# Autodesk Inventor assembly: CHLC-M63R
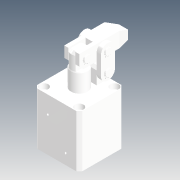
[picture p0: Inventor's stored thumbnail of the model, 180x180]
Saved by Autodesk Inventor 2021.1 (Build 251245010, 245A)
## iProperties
Created: 2019-04
Part Number: CHLC-M63R
Description: STEP AP214
Document SubType Name: Assembly
Designer: user
Title: chlc-m63_asm-R.STEP
Revision Number: ÈÎºÎ
Sending System: SolidWorks 2016
Preprocessor: SwSTEP 2.0
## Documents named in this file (10)
- D:\Vault_2016\Projekty\Clamptek\Hydraulic\CHLC\CHLC-63\Inventor\CHLC-M63R\CHLC-M63R.iam
- D:\Vault_2016\Projekty\Clamptek\Hydraulic\CHLC\CHLC-63\Inventor\CHLC-M63R\CHLC-M63-±¾Ìå.ipt
- D:\Vault_2016\Projekty\Clamptek\Hydraulic\CHLC\CHLC-63\Inventor\CHLC-M63R\CHLC-M63-͹̨00.ipt
- D:\Vault_2016\Projekty\Clamptek\Hydraulic\CHLC\CHLC-63\Inventor\CHLC-M63R\CHLC-63-01.ipt
- D:\Vault_2016\Projekty\Clamptek\Hydraulic\CHLC\CHLC-63\Inventor\CHLC-M63R\CHLC-63-02.ipt
- D:\Vault_2016\Projekty\Clamptek\Hydraulic\CHLC\CHLC-63\Inventor\CHLC-M63R\CHLC-63-03.ipt
- D:\Vault_2016\Projekty\Clamptek\Hydraulic\CHLC\CHLC-63\Inventor\CHLC-M63R\CHLC-63-04.ipt
- D:\Vault_2016\Projekty\Clamptek\Hydraulic\CHLC\CHLC-63\Inventor\CHLC-M63R\CHLC-63-05.ipt
- D:\Vault_2016\Projekty\Clamptek\Hydraulic\CHLC\CHLC-63\Inventor\CHLC-M63R\CHLC-63-07.ipt
- D:\Vault_2016\Projekty\Clamptek\Hydraulic\CHLC\CHLC-63\Inventor\CHLC-M63R\M6LS_1.ipt
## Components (17 placed, 17 different names)
1. CHLC-M63-±¾Ìå_1
2. CHLC-M63-͹̨00_2
3. CHLC-63-01_3
4. CHLC-63-02_4
5. CHLC-63-03_5
6. CHLC-63-04_6
7. CHLC-63-05_7
8. CHLC-63-07_8
9. CHLC-63-04_9
10. CHLC-63-07_10
11. CHLC-63-07_11
12. CHLC-63-03_12
13. CHLC-63-07_13
14. CHLC-63-07_14
15. CHLC-63-07_15
16. M6LS_1_16
17. M6LS_1_17
